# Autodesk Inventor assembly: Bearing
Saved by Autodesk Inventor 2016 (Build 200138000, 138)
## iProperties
ClientObjectVersion: 1
Created: 2016-01
Part Number: Bearing
Document SubType Name: Assembly
Designer: Black Falcon
Author: Black Falcon
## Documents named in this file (2)
- E:\Learning Inventor\Belt Friction Apparatus\Final Assembly\Design Accelerator\Bearing3.iam
- C:\Users\Black Falcon\Documents\Inventor\Content Center Files\R2016\en-US\ANSI SKF RLS(1)\SKFRLS 4 AANSI.ipt
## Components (1 placed, 1 different names)
1. SKF Series RLS RLS 4 A:1
